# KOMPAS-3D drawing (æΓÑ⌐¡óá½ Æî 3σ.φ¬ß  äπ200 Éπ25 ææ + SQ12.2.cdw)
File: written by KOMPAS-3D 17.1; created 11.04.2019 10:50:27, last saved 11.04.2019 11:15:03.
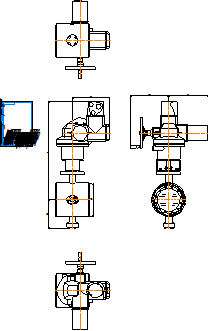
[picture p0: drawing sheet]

Sheet 1: A4, portrait

Title block, sheet 1: name: Стейнвал ТМ 3х.экс / Ду200 Ру25 СС + SQ12.2; material: Внимание! Данный продукт является объектом авторского права ООО «Торговый Дом АДЛ». / Запрещается изменение, копирование, распространение / (в том числе путем копирования на другие сайты и ресурсы в Интернете) / или любое иное использование информации и объектов без предварительного / согласия правообладателя (ООО «Торговый Дом АДЛ»).; mass: 117,36; sheets: 1; organisation: ООО "Торговый дом АДЛ"; sheet format: A4

Views: Вид 1, Проекционный вид 2, Проекционный вид 3
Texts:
  user
Dimensions and other numbers on the sheet: 655; 191,8; 247,8; 219; 1:1; 1; 117,36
